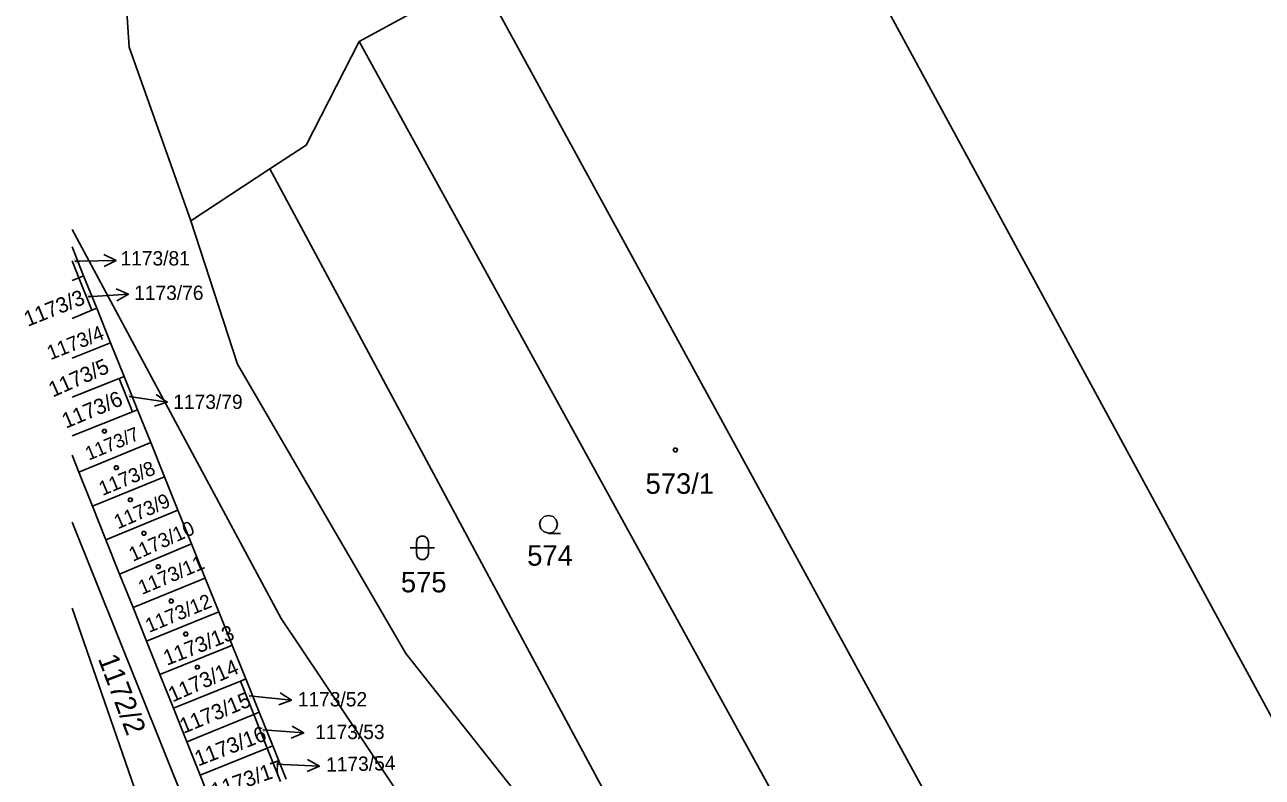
# Model space of a CAD drawing. Extents: x -621797 to -620972, y -1175539 to -1174697.
# Drawn here: x -621794.2 to -621691.5, y -1174884.6 to -1174822.1 of the extents above; entities that cross this region are included whole.
import ezdxf

# ---------------------------------------------------------------- set-up
doc = ezdxf.new("R2010")
doc.units = 0
for name, color, linetype in [('INZ mimo EON - nadz', 7, 'Continuous'), ('Rozvod plynu EON', 7, 'Continuous'), ('SDEL EON', 7, 'Continuous'), ('SDEL EON - popis', 7, 'Continuous'), ('Silnoproud EON', 7, 'Continuous'), ('Silnoproud EON - popis', 7, 'Continuous')]:
    doc.layers.add(name, color=color, linetype=linetype)

msp = doc.modelspace()

# ---------------------------------------------------------------- linework, layer by layer
at = {"layer": 'INZ mimo EON - nadz'}
for p, q in [((-621786.661, -1174841.664), (-621789.66, -1174841.72)), ((-621790.07, -1174841.73), (-621789.66, -1174841.72)), ((-621788.97, -1174844.67), (-621788.62, -1174844.65)), ((-621785.625, -1174844.477), (-621788.62, -1174844.65)), ((-621785.56, -1174852.97), (-621785.38, -1174852.99)), ((-621782.412, -1174853.428), (-621785.38, -1174852.99)), ((-621775.6, -1174877.82), (-621775.09, -1174877.87)), ((-621772.104, -1174878.159), (-621775.09, -1174877.87)), ((-621774.48, -1174880.64), (-621774.08, -1174880.67)), ((-621771.089, -1174880.896), (-621774.08, -1174880.67)), ((-621773.35, -1174883.48), (-621772.78, -1174883.51)), ((-621769.783, -1174883.652), (-621772.78, -1174883.51))]:
    msp.add_line(p, q, dxfattribs=at)
for points in [[(-621787.67, -1174841.183), (-621786.661, -1174841.664), (-621787.651, -1174842.183)], [(-621786.652, -1174844.036), (-621785.625, -1174844.477), (-621786.595, -1174845.034)], [(-621783.328, -1174852.787), (-621782.412, -1174853.428), (-621783.474, -1174853.776)], [(-621773.051, -1174877.565), (-621772.104, -1174878.159), (-621773.147, -1174878.56)], [(-621772.048, -1174880.322), (-621771.089, -1174880.896), (-621772.123, -1174881.319)], [(-621770.759, -1174883.105), (-621769.783, -1174883.652), (-621770.806, -1174884.104)]]:
    msp.add_lwpolyline(points, dxfattribs=at)
at = {"layer": 'Rozvod plynu EON'}
for points in [[(-621787.53, -1174855.69), (-621787.44, -1174855.84), (-621787.53, -1174855.99), (-621787.71, -1174855.99), (-621787.8, -1174855.84), (-621787.71, -1174855.69)], [(-621740.15, -1174857.25), (-621740.06, -1174857.4), (-621740.15, -1174857.55), (-621740.33, -1174857.55), (-621740.42, -1174857.4), (-621740.33, -1174857.25)], [(-621786.54, -1174858.73), (-621786.45, -1174858.88), (-621786.54, -1174859.03), (-621786.72, -1174859.03), (-621786.81, -1174858.88), (-621786.72, -1174858.73)], [(-621785.38, -1174861.39), (-621785.29, -1174861.54), (-621785.38, -1174861.69), (-621785.56, -1174861.69), (-621785.65, -1174861.54), (-621785.56, -1174861.39)], [(-621784.26, -1174864.17), (-621784.17, -1174864.32), (-621784.26, -1174864.47), (-621784.44, -1174864.47), (-621784.53, -1174864.32), (-621784.44, -1174864.17)], [(-621783.06, -1174866.95), (-621782.97, -1174867.1), (-621783.06, -1174867.25), (-621783.24, -1174867.25), (-621783.33, -1174867.1), (-621783.24, -1174866.95)], [(-621781.99, -1174869.8), (-621781.9, -1174869.95), (-621781.99, -1174870.1), (-621782.17, -1174870.1), (-621782.26, -1174869.95), (-621782.17, -1174869.8)], [(-621780.78, -1174872.54), (-621780.69, -1174872.69), (-621780.78, -1174872.84), (-621780.96, -1174872.84), (-621781.05, -1174872.69), (-621780.96, -1174872.54)], [(-621779.82, -1174875.28), (-621779.73, -1174875.43), (-621779.82, -1174875.58), (-621780, -1174875.58), (-621780.09, -1174875.43), (-621780, -1174875.28)]]:
    msp.add_lwpolyline(points, close=True, dxfattribs=at)
at = {"layer": 'SDEL EON'}
for points in [[(-621750.76, -1174864.31), (-621751.14, -1174864.21), (-621751.41, -1174863.94), (-621751.51, -1174863.57), (-621751.41, -1174863.2), (-621751.14, -1174862.93), (-621750.77, -1174862.83), (-621750.4, -1174862.93), (-621750.13, -1174863.2), (-621750.03, -1174863.58), (-621750.13, -1174863.96), (-621750.4, -1174864.23), (-621750.78, -1174864.33), (-621749.78, -1174864.33)], [(-621762.24, -1174865.52), (-621760.97, -1174865.52), (-621760.24, -1174865.52)]]:
    msp.add_lwpolyline(points, dxfattribs=at)
msp.add_lwpolyline([(-621761.74, -1174865.02), (-621761.64, -1174864.73), (-621761.39, -1174864.55), (-621761.08, -1174864.55), (-621760.83, -1174864.73), (-621760.73, -1174865.02), (-621760.73, -1174866.02), (-621760.83, -1174866.31), (-621761.08, -1174866.49), (-621761.39, -1174866.49), (-621761.64, -1174866.31), (-621761.74, -1174866.02)], close=True, dxfattribs=at)
at = {"layer": 'SDEL EON - popis'}
msp.add_line((-621713.24, -1174897.34), (-621756.56, -1174818.04), dxfattribs=at)
at = {"layer": 'Silnoproud EON'}
for p, q in [((-621690, -1174880.99), (-621731.51, -1174804.52)), ((-621785.57, -1174823.97), (-621786.28, -1174812.99)), ((-621756.56, -1174818.04), (-621766.48, -1174823.5)), ((-621780.45, -1174838.37), (-621785.57, -1174823.97)), ((-621766.48, -1174823.5), (-621770.89, -1174832.09)), ((-621723.06, -1174902.46), (-621766.48, -1174823.5)), ((-621770.89, -1174832.09), (-621773.9, -1174834.07)), ((-621773.9, -1174834.07), (-621780.45, -1174838.37)), ((-621737.97, -1174900.96), (-621773.9, -1174834.07)), ((-621776.57, -1174850.27), (-621780.45, -1174838.37)), ((-621790.31, -1174839.11), (-621772.95, -1174871.4)), ((-621790.31, -1174840.554), (-621789.35, -1174842.95)), ((-621790.31, -1174841.712), (-621789.75, -1174843.11)), ((-621790.31, -1174843.332), (-621789.75, -1174843.11)), ((-621789.75, -1174843.11), (-621789.35, -1174842.95)), ((-621789.75, -1174843.11), (-621788.67, -1174845.81)), ((-621789.35, -1174842.95), (-621788.26, -1174845.64)), ((-621788.67, -1174845.81), (-621788.26, -1174845.64)), ((-621788.26, -1174845.64), (-621787.11, -1174848.51)), ((-621790.31, -1174846.491), (-621788.67, -1174845.81)), ((-621787.11, -1174848.51), (-621790.31, -1174849.784)), ((-621787.11, -1174848.51), (-621785.99, -1174851.3)), ((-621762.62, -1174874.29), (-621776.57, -1174850.27)), ((-621790.31, -1174853.016), (-621786.4, -1174851.46)), ((-621786.4, -1174851.46), (-621785.99, -1174851.3)), ((-621786.4, -1174851.46), (-621785.29, -1174854.25)), ((-621785.99, -1174851.3), (-621784.87, -1174854.08)), ((-621790.31, -1174856.242), (-621785.29, -1174854.25)), ((-621785.29, -1174854.25), (-621784.87, -1174854.08)), ((-621784.87, -1174854.08), (-621783.78, -1174856.79)), ((-621789.75, -1174859.25), (-621783.78, -1174856.79)), ((-621783.78, -1174856.79), (-621782.64, -1174859.62)), ((-621789.75, -1174859.25), (-621790.31, -1174857.842)), ((-621788.61, -1174862.08), (-621789.75, -1174859.25)), ((-621782.64, -1174859.62), (-621788.61, -1174862.08)), ((-621782.64, -1174859.62), (-621781.52, -1174862.4)), ((-621787.5, -1174864.86), (-621788.61, -1174862.08)), ((-621781.52, -1174862.4), (-621787.5, -1174864.86)), ((-621781.52, -1174862.4), (-621780.4, -1174865.19)), ((-621790.31, -1174863.397), (-621780.14, -1174888.68)), ((-621786.36, -1174867.7), (-621787.5, -1174864.86)), ((-621786.36, -1174867.7), (-621780.4, -1174865.19)), ((-621780.4, -1174865.19), (-621779.25, -1174868.04)), ((-621785.25, -1174870.48), (-621786.36, -1174867.7)), ((-621785.25, -1174870.48), (-621779.69, -1174868.22)), ((-621779.69, -1174868.22), (-621779.25, -1174868.04)), ((-621779.25, -1174868.04), (-621778.13, -1174870.83)), ((-621790.31, -1174870.521), (-621783.6, -1174889.85)), ((-621784.13, -1174873.27), (-621785.25, -1174870.48)), ((-621784.13, -1174873.27), (-621778.13, -1174870.83)), ((-621778.13, -1174870.83), (-621777.02, -1174873.61)), ((-621772.95, -1174871.4), (-621761.8, -1174888.04)), ((-621783.02, -1174876.05), (-621784.13, -1174873.27)), ((-621783.02, -1174876.05), (-621777.46, -1174873.79)), ((-621777.46, -1174873.79), (-621777.02, -1174873.61)), ((-621777.02, -1174873.61), (-621775.9, -1174876.39)), ((-621751.2, -1174888.69), (-621762.62, -1174874.29)), ((-621781.9, -1174878.83), (-621783.02, -1174876.05)), ((-621781.9, -1174878.83), (-621776.34, -1174876.58)), ((-621776.34, -1174876.58), (-621775.9, -1174876.39)), ((-621776.34, -1174876.58), (-621775.23, -1174879.36)), ((-621775.9, -1174876.39), (-621774.78, -1174879.18)), ((-621780.79, -1174881.62), (-621781.9, -1174878.83)), ((-621780.79, -1174881.62), (-621775.23, -1174879.36)), ((-621775.23, -1174879.36), (-621774.78, -1174879.18)), ((-621775.23, -1174879.36), (-621774.11, -1174882.15)), ((-621774.78, -1174879.18), (-621773.66, -1174881.96)), ((-621779.67, -1174884.4), (-621780.79, -1174881.62)), ((-621779.67, -1174884.4), (-621774.11, -1174882.15)), ((-621774.11, -1174882.15), (-621773.66, -1174881.96)), ((-621774.11, -1174882.15), (-621773, -1174884.93)), ((-621773.66, -1174881.96), (-621772.54, -1174884.74)), ((-621778.56, -1174887.19), (-621779.67, -1174884.4))]:
    msp.add_line(p, q, dxfattribs=at)

# ---------------------------------------------------------------- texts
at = {"layer": 'INZ mimo EON - nadz'}
for s, p in [('1173/81', (-621786.289, -1174842.09)), ('1173/76', (-621785.156, -1174844.95)), ('1173/79', (-621781.906, -1174854)), ('1173/52', (-621771.578, -1174878.69)), ('1173/53', (-621770.128, -1174881.4))]:
    msp.add_text(s, height=1.19, dxfattribs=at).set_placement(p)
msp.add_text('1173/54', height=1.19, rotation=1.3751, dxfattribs=at).set_placement((-621769.216, -1174884.111))
at = {"layer": 'Silnoproud EON - popis'}
for s, height, rotation, p in [('1173/81', 0.1, 292.38036, (-621790.156, -1174841.521)), ('1173/3', 1.28, 21.82969, (-621793.988, -1174847.187)), ('1173/76', 0.1, 295.70352, (-621789.075, -1174844.452)), ('1173/4', 1.2, 21.60051, (-621792.102, -1174849.958)), ('1173/5', 1.28, 23.89234, (-621791.903, -1174853.053)), ('1173/6', 1.28, 22.57454, (-621790.825, -1174855.644)), ('1173/79', 0.1, 291.00526, (-621785.647, -1174852.744)), ('1173/7', 1.14, 22.51724, (-621788.927, -1174858.292)), ('1173/8', 1.19, 22.40265, (-621787.786, -1174861.225)), ('1173/9', 1.19, 23.60586, (-621786.508, -1174864)), ('1173/10', 1.19, 24.408, (-621785.26, -1174866.696)), ('1173/11', 1.19, 22.97561, (-621784.507, -1174869.443)), ('1173/12', 1.19, 22.40265, (-621783.926, -1174872.597)), ('1173/13', 1.27, 21.42862, (-621782.437, -1174875.323)), ('1172/2', 1.7, 290.71879, (-621788.181, -1174874.717)), ('1173/14', 1.27, 23.77775, (-621781.978, -1174878.369)), ('1173/15', 1.28, 22.34535, (-621781.069, -1174880.975)), ('1173/52', 0.1, 292.72414, (-621775.697, -1174877.588)), ('1173/16', 1.28, 20.97026, (-621779.842, -1174883.678)), ('1173/53', 0.1, 291.11986, (-621774.571, -1174880.404)), ('1173/17', 1.28, 19.42327, (-621778.5, -1174886.365)), ('1173/54', 0.1, 297.42239, (-621773.464, -1174883.26))]:
    msp.add_text(s, height=height, rotation=rotation, dxfattribs=at).set_placement(p)
for s, p in [('573/1', (-621742.723, -1174861.04)), ('574', (-621752.543, -1174867.01)), ('575', (-621763.023, -1174869.22))]:
    msp.add_text(s, height=1.7, dxfattribs=at).set_placement(p)

doc.saveas('drawing.dxf')
